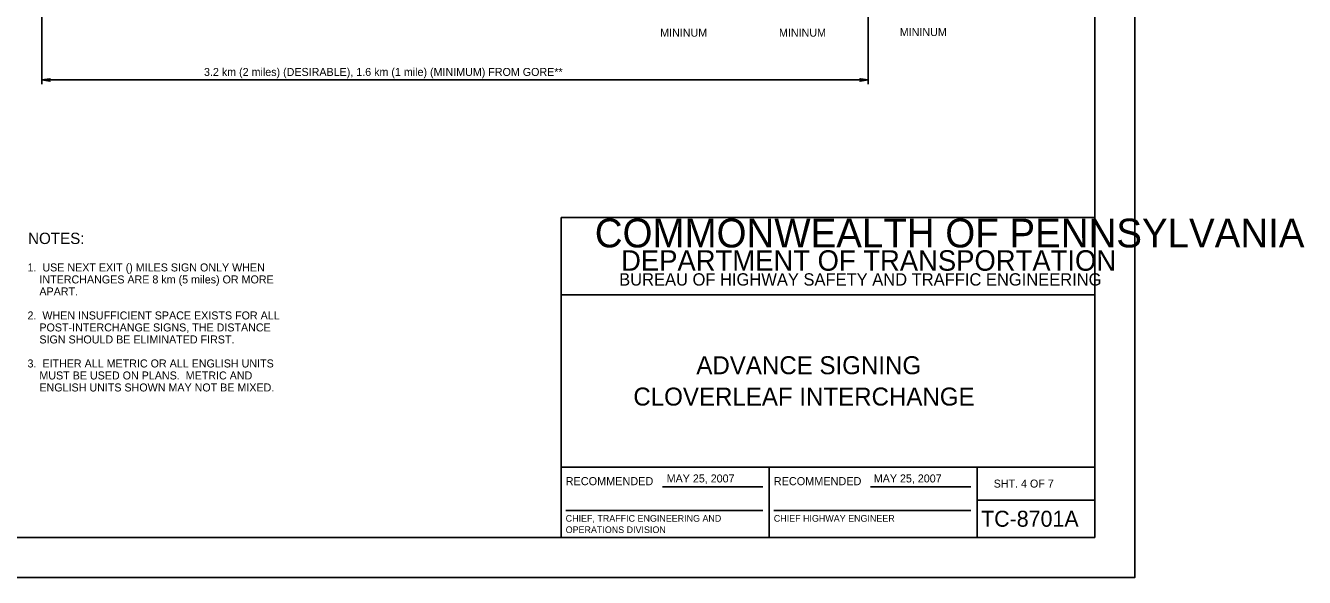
# Model space of a CAD drawing. Extents: x 640994 to 644422, y 298458 to 299646.
# Drawn here: x 643942.6 to 644421.9, y 299051.6 to 299258.5 of the extents above; entities that cross this region are included whole.
import ezdxf

# ---------------------------------------------------------------- set-up
doc = ezdxf.new("R2010")
doc.units = 0
for name, color, linetype in [('1', 7, 'Continuous'), ('2', 7, 'Continuous'), ('XCS-GRID-MIN', 7, 'Continuous')]:
    doc.layers.add(name, color=color, linetype=linetype)

msp = doc.modelspace()

# ---------------------------------------------------------------- linework, layer by layer
at = {"layer": '1'}
for p, q in [((644343.31, 299066.63), (644343.31, 299630.63)), ((644143.31, 299066.63), (644143.31, 299186.63)), ((644143.31, 299186.63), (644343.31, 299186.63)), ((644343.31, 299157.63), (644143.31, 299157.63)), ((644143.31, 299093), (644343.31, 299093)), ((644221.31, 299093), (644221.31, 299066.63)), ((644299.19, 299066.63), (644299.19, 299093)), ((644181.24, 299085.57), (644218.87, 299085.57)), ((644259.24, 299085.57), (644296.87, 299085.57)), ((644299.19, 299080.63), (644343.31, 299080.63)), ((644144.99, 299076.68), (644218.87, 299076.68)), ((644222.99, 299076.68), (644296.87, 299076.68)), ((644343.31, 299066.63), (643557.31, 299066.63)), ((643557.31, 299066.63), (644143.31, 299066.63))]:
    msp.add_line(p, q, dxfattribs=at)
at = {"layer": '2'}
for p, q in [((644258.31, 299314.64), (644258.31, 299236.52)), ((643948.69, 299311.52), (643948.69, 299236.52)), ((643948.69, 299238.14), (644258.31, 299238.14))]:
    msp.add_line(p, q, dxfattribs=at)
for points in [[(643951.54, 299237.78), (643951.43, 299237.99), (643948.69, 299238.14), (643951.54, 299237.78), (643951.69, 299237.66), (643948.69, 299238.14), (643951.43, 299238.28), (643951.53, 299238.48), (643948.69, 299238.14), (643951.69, 299238.62), (643951.53, 299238.48)], [(644255.46, 299238.5), (644255.56, 299238.29), (644258.31, 299238.14), (644255.46, 299238.5), (644255.31, 299238.62), (644258.31, 299238.14), (644255.57, 299238.01), (644255.47, 299237.8), (644258.31, 299238.14), (644255.31, 299237.66), (644255.47, 299237.8)]]:
    msp.add_lwpolyline(points, dxfattribs=at)
at = {"layer": 'XCS-GRID-MIN'}
msp.add_lwpolyline([(643517.31, 299645.63), (644358.31, 299645.63), (644358.31, 299051.63), (643517.31, 299051.63)], close=True, dxfattribs=at)

# ---------------------------------------------------------------- texts
at = {"layer": '1'}
for s, height, p in [('COMMONWEALTH OF PENNSYLVANIA', 10.7828, (644155.9, 299175.36)), ('DEPARTMENT OF TRANSPORTATION', 7.6837, (644165.76, 299166.61)), ('BUREAU OF HIGHWAY SAFETY AND TRAFFIC ENGINEERING', 4.6253, (644165.04, 299161.04)), ('ADVANCE SIGNING', 6.75, (644193.96, 299127.81)), ('CLOVERLEAF INTERCHANGE', 6.75, (644170.36, 299116.06)), ('RECOMMENDED', 3.048, (644144.99, 299086.2)), ('RECOMMENDED', 3.048, (644222.99, 299086.2)), ('SHT. 4 OF 7', 3, (644305.4, 299085.31)), ('CHIEF, TRAFFIC ENGINEERING AND', 2.5, (644144.99, 299072.51)), ('CHIEF HIGHWAY ENGINEER', 2.5, (644222.99, 299072.51)), ('TC-8701A', 6, (644300.68, 299070.63)), ('OPERATIONS DIVISION', 2.5, (644144.99, 299068.26))]:
    msp.add_text(s, height=height, dxfattribs=at).set_placement(p)
at = {"layer": '2'}
for s, height, p in [(' MININUM', 3, (644179.3, 299254.36)), (' MININUM', 3, (644223.83, 299254.36)), (' MININUM', 3, (644269.09, 299254.6)), ('3.2 km (2 miles) (DESIRABLE), 1.6 km (1 mile) (MINIMUM) FROM GORE**', 3, (644009.44, 299239.64)), ('NOTES:', 4.25, (643943.5, 299176.63)), ('1.  USE NEXT EXIT () MILES SIGN ONLY WHEN', 3, (643943.29, 299166.35)), ('    INTERCHANGES ARE 8 km (5 miles) OR MORE', 3, (643943.29, 299161.85)), ('    APART.', 3, (643943.29, 299157.35)), ('2.  WHEN INSUFFICIENT SPACE EXISTS FOR ALL', 3, (643943.29, 299148.35)), ('    POST-INTERCHANGE SIGNS, THE DISTANCE', 3, (643943.29, 299143.85)), ('    SIGN SHOULD BE ELIMINATED FIRST.', 3, (643943.29, 299139.35)), ('3.  EITHER ALL METRIC OR ALL ENGLISH UNITS', 3, (643943.29, 299130.35)), ('    MUST BE USED ON PLANS.  METRIC AND', 3, (643943.29, 299125.85)), ('    ENGLISH UNITS SHOWN MAY NOT BE MIXED.', 3, (643943.29, 299121.35)), ('MAY 25, 2007', 3, (644182.85, 299087.24))]:
    msp.add_text(s, height=height, dxfattribs=at).set_placement(p)
msp.add_text('MAY 25, 2007', height=3, rotation=360, dxfattribs=at).set_placement((644260.47, 299087.24))

doc.saveas('drawing.dxf')
